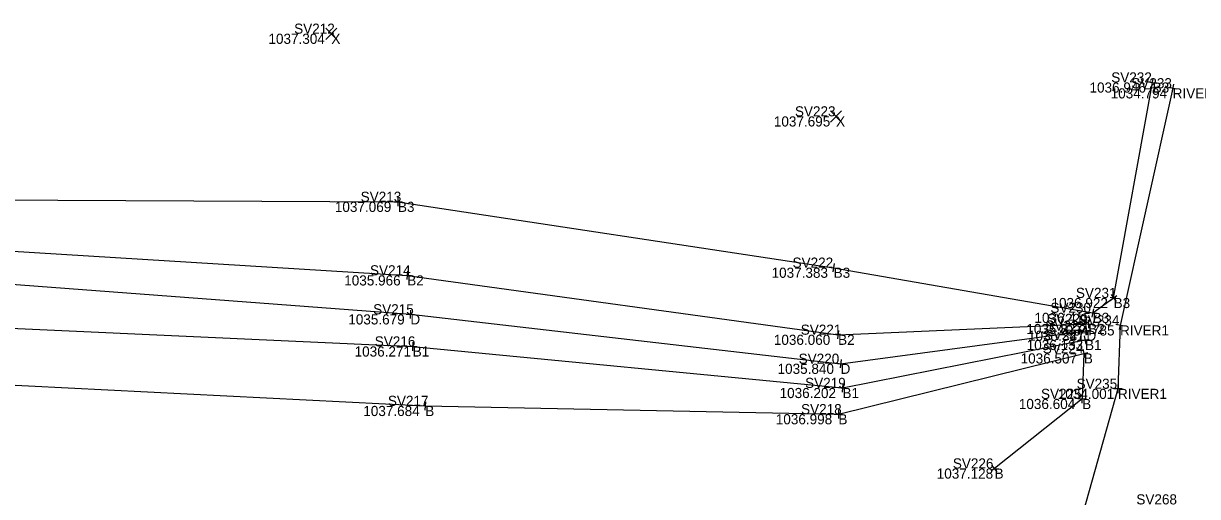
# Model space of a CAD drawing. Extents: x 1542529 to 1609210, y 587215 to 645373.
# Drawn here: x 1608791 to 1608930.2, y 645275.5 to 645331.6 of the extents above; entities that cross this region are included whole.
import ezdxf

# ---------------------------------------------------------------- set-up
doc = ezdxf.new("R2010")
doc.units = 0
for name, color, linetype in [('DR_X_Ditch', 7, 'Continuous'), ('HY_X_Water_Edge', 7, 'Continuous'), ('SV_X_Random_Point', 7, 'Continuous'), ('SV_X_Shot_Marker', 7, 'Continuous'), ('SV_X_Text_Comment', 7, 'Continuous'), ('SV_X_Text_Elevation', 7, 'Continuous'), ('SV_X_Text_Name', 7, 'Continuous'), ('SV_X_Toe_of_Slope', 7, 'Continuous'), ('SV_X_Top_of_Bank', 7, 'Continuous')]:
    doc.layers.add(name, color=color, linetype=linetype)

msp = doc.modelspace()

# ---------------------------------------------------------------- linework, layer by layer
at = {"layer": 'DR_X_Ditch'}
msp.add_lwpolyline([(1608662.8, 645291.41), (1608724.04, 645294.47), (1608780.04, 645301.36), (1608836.85, 645297.07), (1608887.88, 645291.21), (1608917.04, 645295.13)], dxfattribs=at)
at = {"layer": 'HY_X_Water_Edge'}
msp.add_lwpolyline([(1608927.27, 645323.87), (1608921.03, 645295.76), (1608920.78, 645288.24), (1608903.17, 645225.66)], dxfattribs=at)
at = {"layer": 'SV_X_Random_Point'}
for p, q in [((1608826.81, 645329.67), (1608828.14, 645331)), ((1608826.81, 645331), (1608828.14, 645329.67)), ((1608886.67, 645319.87), (1608888, 645321.21)), ((1608886.67, 645321.21), (1608888, 645319.87))]:
    msp.add_line(p, q, dxfattribs=at)
at = {"layer": 'SV_X_Shot_Marker'}
for p, q in [((1608924.39, 645324.65), (1608925.38, 645324.47)), ((1608924.8, 645324.07), (1608924.97, 645325.05)), ((1608924.89, 645324.56), (1608924.89, 645324.56)), ((1608927.76, 645323.76), (1608926.78, 645323.98)), ((1608927.38, 645324.36), (1608927.16, 645323.38)), ((1608927.27, 645323.87), (1608927.27, 645323.87)), ((1608835.37, 645310.91), (1608835.37, 645309.91)), ((1608834.87, 645310.41), (1608835.87, 645310.41)), ((1608835.37, 645310.41), (1608835.37, 645310.41)), ((1608886.55, 645302.67), (1608887.54, 645302.52)), ((1608887.12, 645303.09), (1608886.97, 645302.1)), ((1608887.05, 645302.6), (1608887.05, 645302.6)), ((1608835.97, 645301.72), (1608836.97, 645301.66)), ((1608836.5, 645302.19), (1608836.44, 645301.19)), ((1608836.47, 645301.69), (1608836.47, 645301.69)), ((1608919.97, 645299.41), (1608920.55, 645298.6)), ((1608919.85, 645298.72), (1608920.66, 645299.29)), ((1608920.26, 645299.01), (1608920.26, 645299.01)), ((1608836.35, 645297.1), (1608837.35, 645297.03)), ((1608836.88, 645297.56), (1608836.81, 645296.57)), ((1608836.85, 645297.07), (1608836.85, 645297.07)), ((1608917.29, 645297.33), (1608918.27, 645297.16)), ((1608917.87, 645297.74), (1608917.69, 645296.75)), ((1608917.78, 645297.25), (1608917.78, 645297.25)), ((1608916.75, 645295.9), (1608917.75, 645295.95)), ((1608916.98, 645295.62), (1608917.11, 645294.63)), ((1608917.23, 645296.43), (1608917.27, 645295.43)), ((1608917.25, 645295.93), (1608917.25, 645295.93)), ((1608921.52, 645295.65), (1608920.54, 645295.87)), ((1608921.14, 645296.25), (1608920.92, 645295.27)), ((1608921.03, 645295.76), (1608921.03, 645295.76)), ((1608887.08, 645294.72), (1608888.07, 645294.58)), ((1608887.64, 645295.15), (1608887.51, 645294.16)), ((1608887.58, 645294.65), (1608887.58, 645294.65)), ((1608916.38, 645293.93), (1608917.36, 645294.12)), ((1608916.55, 645295.06), (1608917.54, 645295.19)), ((1608916.77, 645294.52), (1608916.97, 645293.54)), ((1608916.87, 645294.03), (1608916.87, 645294.03)), ((1608917.04, 645295.13), (1608917.04, 645295.13)), ((1608836.62, 645293.28), (1608837.62, 645293.24)), ((1608837.14, 645293.76), (1608837.09, 645292.76)), ((1608837.12, 645293.26), (1608837.12, 645293.26)), ((1608916.24, 645292.32), (1608917.21, 645292.56)), ((1608916.61, 645292.93), (1608916.85, 645291.96)), ((1608916.73, 645292.44), (1608916.73, 645292.44)), ((1608887.38, 645291.27), (1608888.37, 645291.15)), ((1608887.93, 645291.7), (1608887.82, 645290.71)), ((1608887.88, 645291.21), (1608887.88, 645291.21)), ((1608887.61, 645288.39), (1608888.6, 645288.29)), ((1608888.15, 645288.84), (1608888.05, 645287.85)), ((1608888.1, 645288.34), (1608888.1, 645288.34)), ((1608920.8, 645288.74), (1608920.77, 645287.74)), ((1608917.03, 645287.02), (1608916.03, 645287.05)), ((1608916.54, 645287.54), (1608916.51, 645286.54)), ((1608916.53, 645287.04), (1608916.53, 645287.04)), ((1608921.28, 645288.22), (1608920.28, 645288.25)), ((1608920.78, 645288.24), (1608920.78, 645288.24)), ((1608838.11, 645286.24), (1608839.11, 645286.19)), ((1608838.63, 645286.71), (1608838.58, 645285.71)), ((1608838.61, 645286.21), (1608838.61, 645286.21)), ((1608887.63, 645285.73), (1608887.61, 645284.73)), ((1608887.12, 645285.24), (1608888.12, 645285.22)), ((1608887.62, 645285.23), (1608887.62, 645285.23)), ((1608906.53, 645279.1), (1608905.75, 645278.48)), ((1608906.45, 645278.4), (1608905.83, 645279.18)), ((1608906.14, 645278.79), (1608906.14, 645278.79))]:
    msp.add_line(p, q, dxfattribs=at)
at = {"layer": 'SV_X_Toe_of_Slope'}
for points in [[(1608662.22, 645295.24), (1608723.58, 645300.63), (1608779.4, 645305.18), (1608836.47, 645301.69), (1608887.58, 645294.65), (1608917.25, 645295.93)], [(1608663.72, 645285.32), (1608725.25, 645289.58), (1608780.72, 645295.81), (1608837.12, 645293.26), (1608888.1, 645288.34), (1608916.87, 645294.03)]]:
    msp.add_lwpolyline(points, dxfattribs=at)
at = {"layer": 'SV_X_Top_of_Bank'}
for points in [[(1608661.8, 645301.18), (1608723.2, 645308.3), (1608778.85, 645310.68), (1608835.37, 645310.41), (1608887.05, 645302.6), (1608917.78, 645297.25), (1608920.26, 645299.01), (1608924.89, 645324.56)], [(1608664.98, 645275.74), (1608726, 645282.99), (1608782.09, 645289.07), (1608838.61, 645286.21), (1608887.62, 645285.23), (1608916.73, 645292.44), (1608916.53, 645287.04), (1608906.14, 645278.79)]]:
    msp.add_lwpolyline(points, dxfattribs=at)

# ---------------------------------------------------------------- texts
at = {"layer": 'SV_X_Text_Comment'}
for s, p in [('X', (1608827.47, 645329.14)), ('B3', (1608924.89, 645323.36)), ('RIVER1', (1608927.27, 645322.67)), ('X', (1608887.34, 645319.34)), ('B3', (1608835.37, 645309.21)), ('B3', (1608887.05, 645301.4)), ('B2', (1608836.47, 645300.49)), ('B3', (1608920.26, 645297.81)), ('D', (1608836.85, 645295.87)), ('B3', (1608917.78, 645296.05)), ('B2', (1608917.25, 645294.73)), ('RIVER1', (1608921.03, 645294.56)), ('B2', (1608887.58, 645293.45)), ('B1', (1608916.87, 645292.83)), ('D', (1608917.04, 645293.93)), ('B1', (1608837.12, 645292.06)), ('B', (1608916.73, 645291.24)), ('D', (1608887.88, 645290.01)), ('B1', (1608888.1, 645287.14)), ('B', (1608916.53, 645285.84)), ('RIVER1', (1608920.78, 645287.04)), ('B', (1608838.61, 645285.01)), ('B', (1608887.62, 645284.03)), ('B', (1608906.14, 645277.59))]:
    msp.add_text(s, height=1.2, dxfattribs=at).set_placement(p)
at = {"layer": 'SV_X_Text_Elevation'}
for s, p in [('1037.304', (1608820.01, 645329.14)), ('1036.946', (1608917.4, 645323.36)), ('1034.794', (1608919.91, 645322.67)), ('1037.695', (1608879.96, 645319.34)), ('1037.069', (1608827.89, 645309.21)), ('1037.383', (1608879.69, 645301.4)), ('1035.966', (1608829, 645300.49)), ('1036.922', (1608912.89, 645297.81)), ('1035.679', (1608829.48, 645295.87)), ('1036.415', (1608910.87, 645296.05)), ('1035.827', (1608909.91, 645294.73)), ('1034.785', (1608913.68, 645294.56)), ('1036.060', (1608879.96, 645293.45)), ('1036.133', (1608909.95, 645292.83)), ('1035.341', (1608910.11, 645293.93)), ('1036.271', (1608830.23, 645292.06)), ('1036.507', (1608909.23, 645291.24)), ('1035.840', (1608880.4, 645290.01)), ('1036.202', (1608880.64, 645287.14)), ('1036.604', (1608909.02, 645285.84)), ('1034.001', (1608913.64, 645287.04)), ('1037.684', (1608831.26, 645285.01)), ('1036.998', (1608880.19, 645284.03)), ('1037.128', (1608899.28, 645277.59))]:
    msp.add_text(s, height=1.2, dxfattribs=at).set_placement(p)
at = {"layer": 'SV_X_Text_Name'}
for s, p in [('SV212', (1608823.06, 645330.34)), ('SV232', (1608919.98, 645324.56)), ('SV233', (1608922.36, 645323.87)), ('SV223', (1608882.46, 645320.54)), ('SV213', (1608830.95, 645310.41)), ('SV222', (1608882.18, 645302.6)), ('SV214', (1608832.06, 645301.69)), ('SV231', (1608915.79, 645299.01)), ('SV215', (1608832.43, 645297.07)), ('SV230', (1608912.76, 645297.25)), ('SV229', (1608912.36, 645295.93)), ('SV234', (1608916.13, 645295.76)), ('SV221', (1608883.15, 645294.65)), ('SV227', (1608912, 645294.03)), ('SV228', (1608912.16, 645295.13)), ('SV216', (1608832.62, 645293.26)), ('SV224', (1608911.86, 645292.44)), ('SV220', (1608882.9, 645291.21)), ('SV219', (1608883.67, 645288.34)), ('SV235', (1608915.87, 645288.24)), ('SV217', (1608834.18, 645286.21)), ('SV225', (1608911.65, 645287.04)), ('SV218', (1608883.19, 645285.23)), ('SV226', (1608901.19, 645278.79)), ('SV268', (1608922.96, 645274.53))]:
    msp.add_text(s, height=1.2, dxfattribs=at).set_placement(p)

doc.saveas('drawing.dxf')
